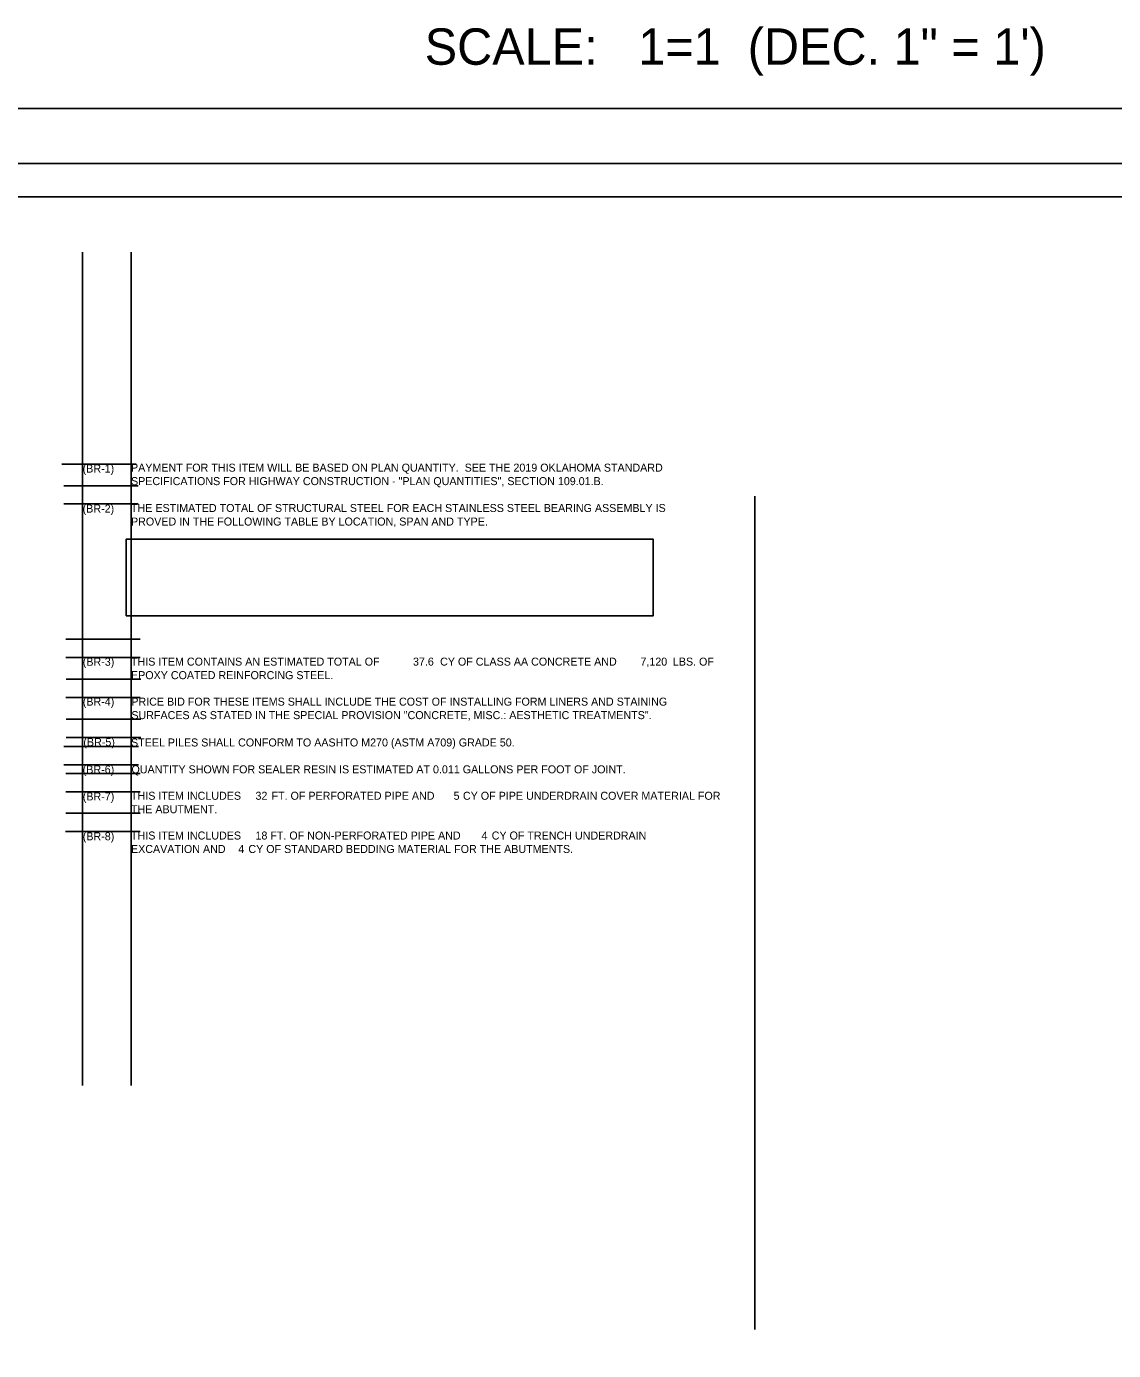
# Model space of a CAD drawing. Extents: x 12303.1 to 12355.9, y 579 to 640.5.
# Drawn here: x 12323.32 to 12339.62, y 589.98 to 609.83 of the extents above; entities that cross this region are included whole.
import ezdxf

# ---------------------------------------------------------------- set-up
doc = ezdxf.new("R2010")
doc.units = 0
for name, color, linetype in [('S', 7, 'Continuous'), ('SHT_Plot_Shape_Full', 7, 'Continuous'), ('SHT_Plot_Shape_Half', 7, 'Continuous'), ('SHT_Sheet_Border', 7, 'Continuous'), ('T', 7, 'Continuous')]:
    doc.layers.add(name, color=color, linetype=linetype)

msp = doc.modelspace()

# ---------------------------------------------------------------- linework, layer by layer
at = {"layer": 'Defpoints'}
for p, q in [((12324.161, 593.954), (12324.161, 606.446)), ((12324.886, 606.446), (12324.886, 593.954)), ((12324.963, 603.269), (12323.847, 603.269)), ((12324.993, 602.944), (12323.878, 602.944)), ((12324.993, 602.67), (12323.878, 602.67)), ((12334.24, 590.293), (12334.24, 602.785)), ((12325.023, 600.642), (12323.907, 600.642)), ((12325.023, 600.367), (12323.907, 600.367)), ((12325.031, 600.044), (12323.916, 600.044)), ((12325.023, 599.77), (12323.907, 599.77)), ((12325.031, 599.445), (12323.916, 599.445)), ((12325.031, 599.171), (12323.916, 599.171)), ((12324.997, 599.035), (12323.881, 599.035)), ((12324.997, 598.761), (12323.881, 598.761)), ((12325.022, 598.632), (12323.907, 598.632)), ((12325.022, 598.357), (12323.907, 598.357)), ((12325.024, 598.034), (12323.908, 598.034)), ((12325.02, 597.76), (12323.904, 597.76)), ((12325.022, 597.76), (12323.907, 597.76))]:
    msp.add_line(p, q, dxfattribs=at)
at = {"layer": 'SHT_Plot_Shape_Full'}
msp.add_lwpolyline([(12316.36, 608.6), (12352.36, 608.6), (12352.36, 584.6), (12316.36, 584.6)], close=True, dxfattribs=at)
at = {"layer": 'SHT_Plot_Shape_Half'}
msp.add_lwpolyline([(12317.998, 607.775), (12351.998, 607.775), (12351.998, 585.775), (12317.998, 585.775)], close=True, dxfattribs=at)
at = {"layer": 'SHT_Sheet_Border'}
msp.add_lwpolyline([(12351.448, 586.275), (12319.948, 586.275), (12319.948, 607.275), (12351.448, 607.275)], close=True, dxfattribs=at)
at = {"layer": 'T'}
msp.add_lwpolyline([(12324.813, 600.995), (12332.716, 600.995), (12332.716, 602.141), (12324.813, 602.141)], close=True, dxfattribs=at)

# ---------------------------------------------------------------- texts
at = {"layer": 'S'}
msp.add_text('SCALE:   1=1  (DEC. 1" = 1\')', height=0.54513, dxfattribs=at).set_placement((12329.289, 609.255))
at = {"layer": 'T'}
for s, p in [('(BR-1)', (12324.161, 603.141)), ('PAYMENT FOR THIS ITEM WILL BE BASED ON PLAN QUANTITY.  SEE THE 2019 OKLAHOMA STANDARD ', (12324.886, 603.155)), ('SPECIFICATIONS FOR HIGHWAY CONSTRUCTION - "PLAN QUANTITIES", SECTION 109.01.B.', (12324.886, 602.953)), ('(BR-2)', (12324.161, 602.541)), ('THE ESTIMATED TOTAL OF STRUCTURAL STEEL FOR EACH STAINLESS STEEL BEARING ASSEMBLY IS ', (12324.886, 602.55)), ('PROVED IN THE FOLLOWING TABLE BY LOCATION, SPAN AND TYPE.', (12324.886, 602.347)), ('(BR-3)', (12324.163, 600.245)), ('THIS ITEM CONTAINS AN ESTIMATED TOTAL OF ', (12324.886, 600.247)), ('37.6', (12329.113, 600.247)), (' CY OF CLASS AA CONCRETE AND ', (12329.475, 600.247)), ('7,120', (12332.523, 600.247)), (' LBS. OF ', (12332.965, 600.247)), ('EPOXY COATED REINFORCING STEEL.', (12324.886, 600.044)), ('(BR-4)', (12324.163, 599.647)), ('PRICE BID FOR THESE ITEMS SHALL INCLUDE THE COST OF INSTALLING FORM LINERS AND STAINING ', (12324.891, 599.647)), ('SURFACES AS STATED IN THE SPECIAL PROVISION "CONCRETE, MISC.: AESTHETIC TREATMENTS".', (12324.891, 599.445)), ('(BR-5)', (12324.172, 599.041)), ('STEEL PILES SHALL CONFORM TO AASHTO M270 (ASTM A709) GRADE 50.', (12324.886, 599.035)), ('(BR-6)', (12324.162, 598.63)), ('QUANTITY SHOWN FOR SEALER RESIN IS ESTIMATED AT 0.011 GALLONS PER FOOT OF JOINT.', (12324.893, 598.632)), ('(BR-7)', (12324.163, 598.226)), ('THIS ITEM INCLUDES ', (12324.886, 598.236)), ('32', (12326.752, 598.236)), (' FT. OF PERFORATED PIPE AND ', (12326.948, 598.236)), ('5', (12329.722, 598.236)), (' CY OF PIPE UNDERDRAIN COVER MATERIAL FOR ', (12329.818, 598.236)), ('THE ABUTMENT. ', (12324.886, 598.034)), ('(BR-8)', (12324.163, 597.628)), ('THIS ITEM INCLUDES ', (12324.886, 597.64)), ('18', (12326.752, 597.64)), (' FT. OF NON-PERFORATED PIPE AND ', (12326.93, 597.64)), ('4', (12330.141, 597.64)), (' CY OF TRENCH UNDERDRAIN ', (12330.249, 597.64)), ('EXCAVATION AND ', (12324.886, 597.438)), ('4', (12326.494, 597.438)), (' CY OF STANDARD BEDDING MATERIAL FOR THE ABUTMENTS.  ', (12326.601, 597.438))]:
    msp.add_text(s, height=0.12, dxfattribs=at).set_placement(p)

doc.saveas('drawing.dxf')
